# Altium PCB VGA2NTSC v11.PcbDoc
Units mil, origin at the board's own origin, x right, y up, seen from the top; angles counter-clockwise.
Board outline 2300 x 4000 mil, 2 copper layers (Top Layer, Bottom Layer), stack 62.8 mil thick; 49 components, 41 nets, 184 pads, 29 vias.
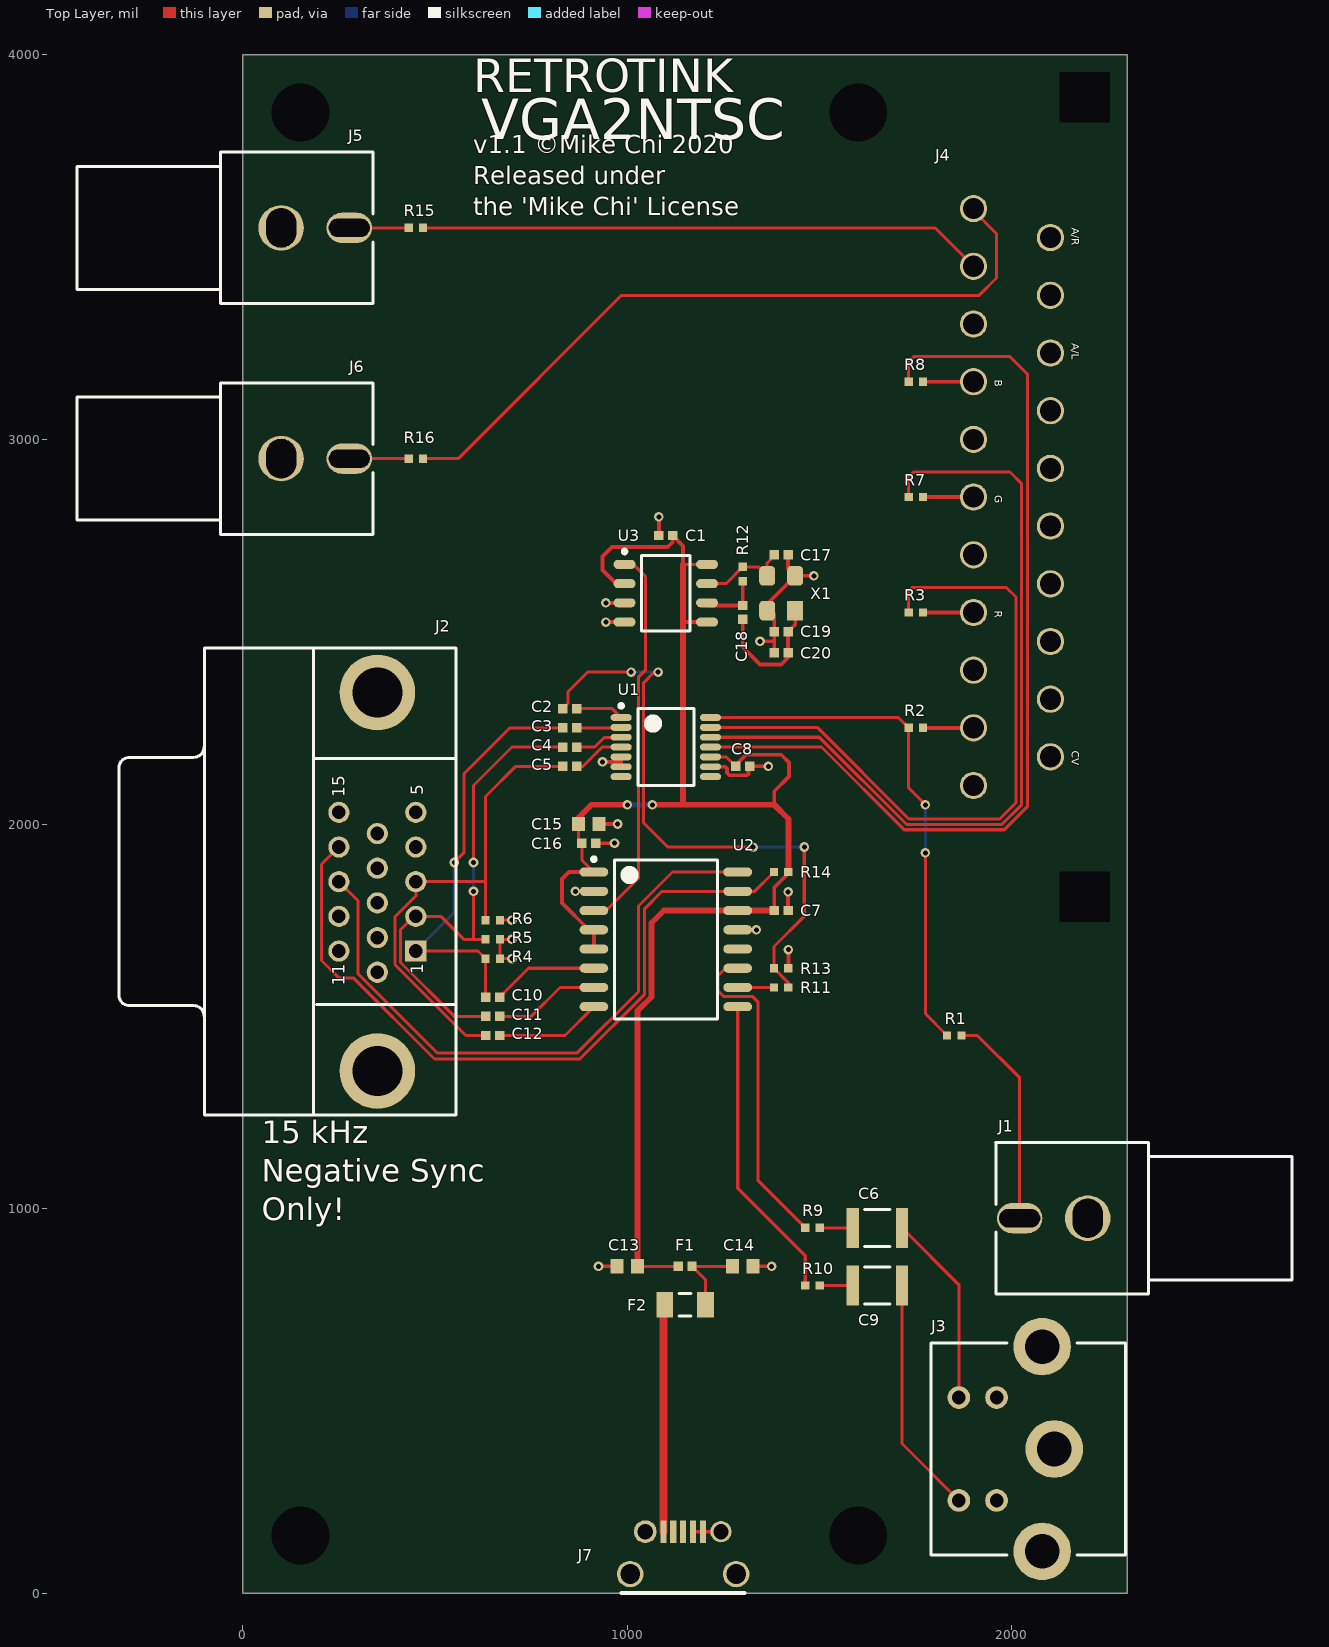
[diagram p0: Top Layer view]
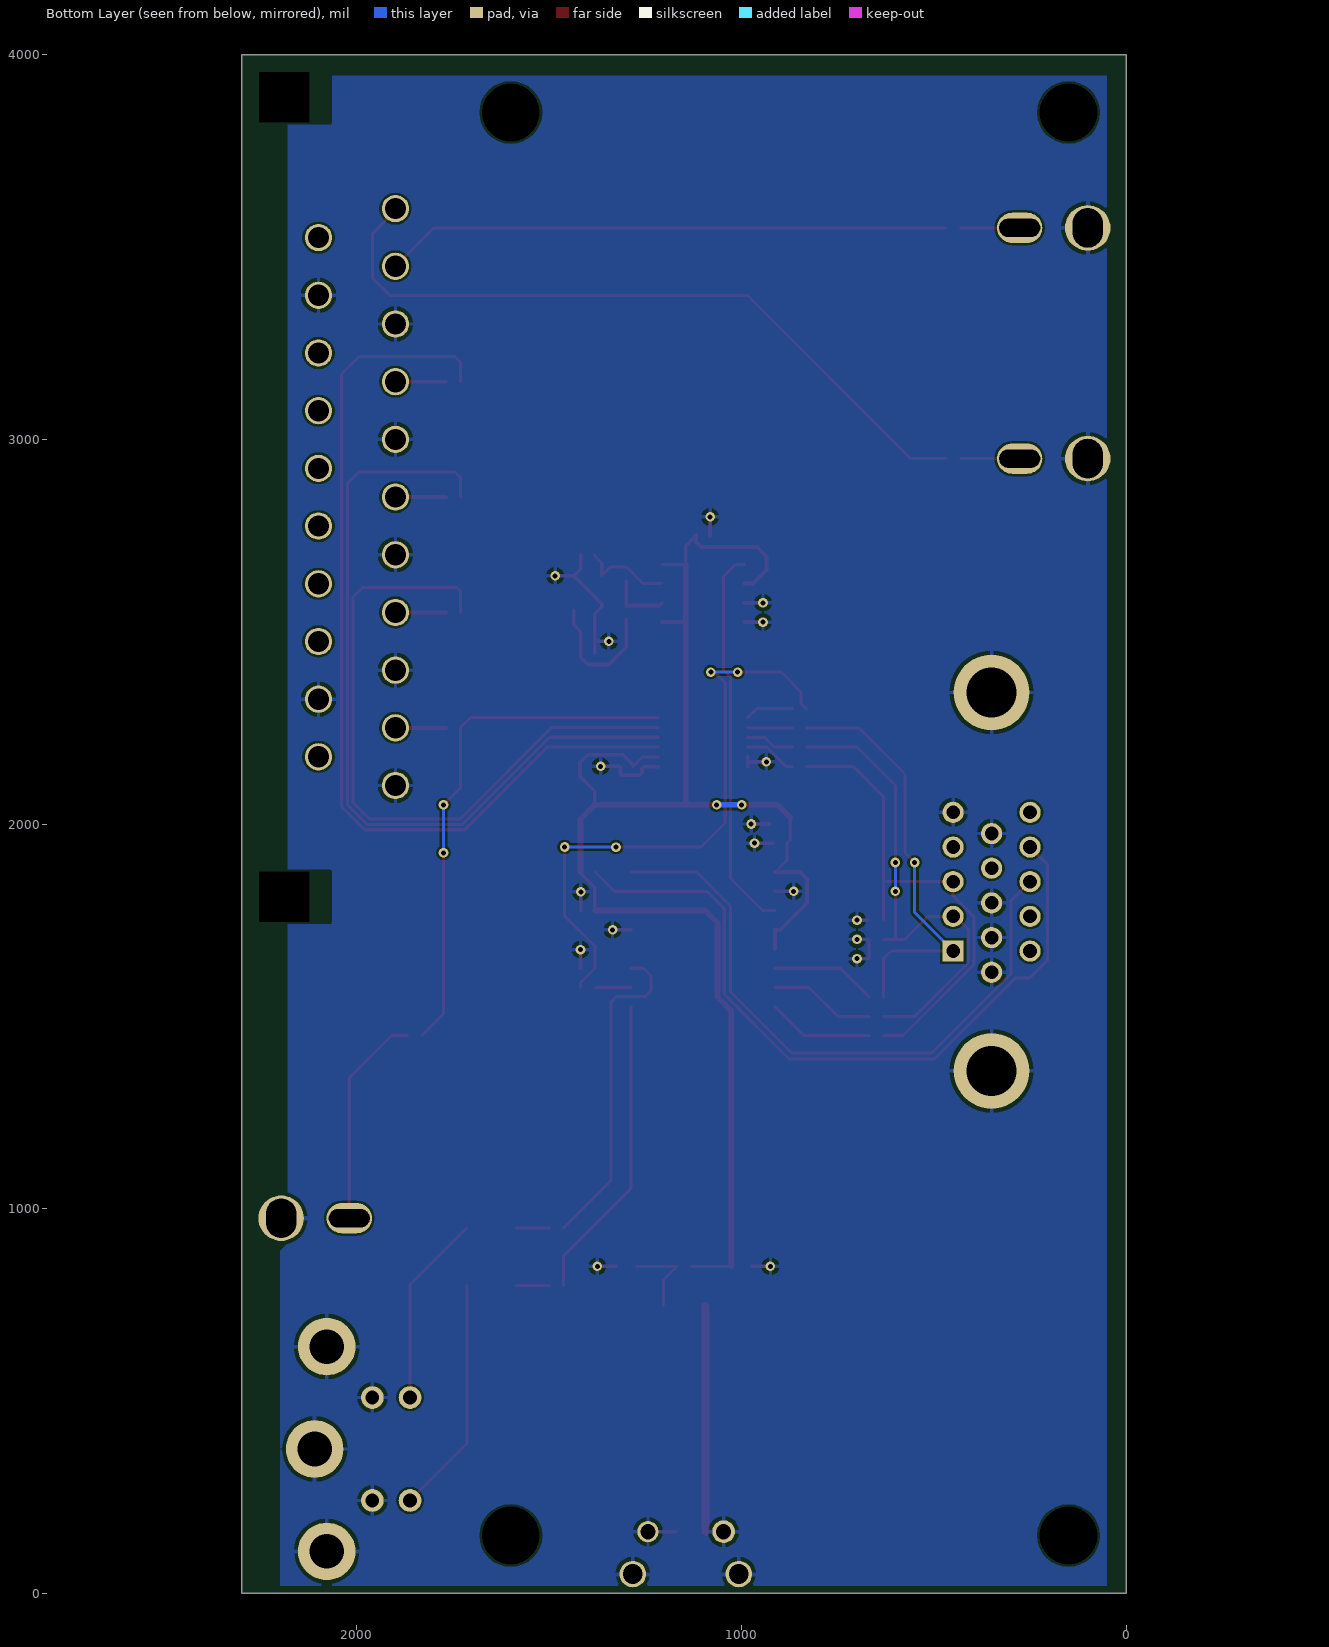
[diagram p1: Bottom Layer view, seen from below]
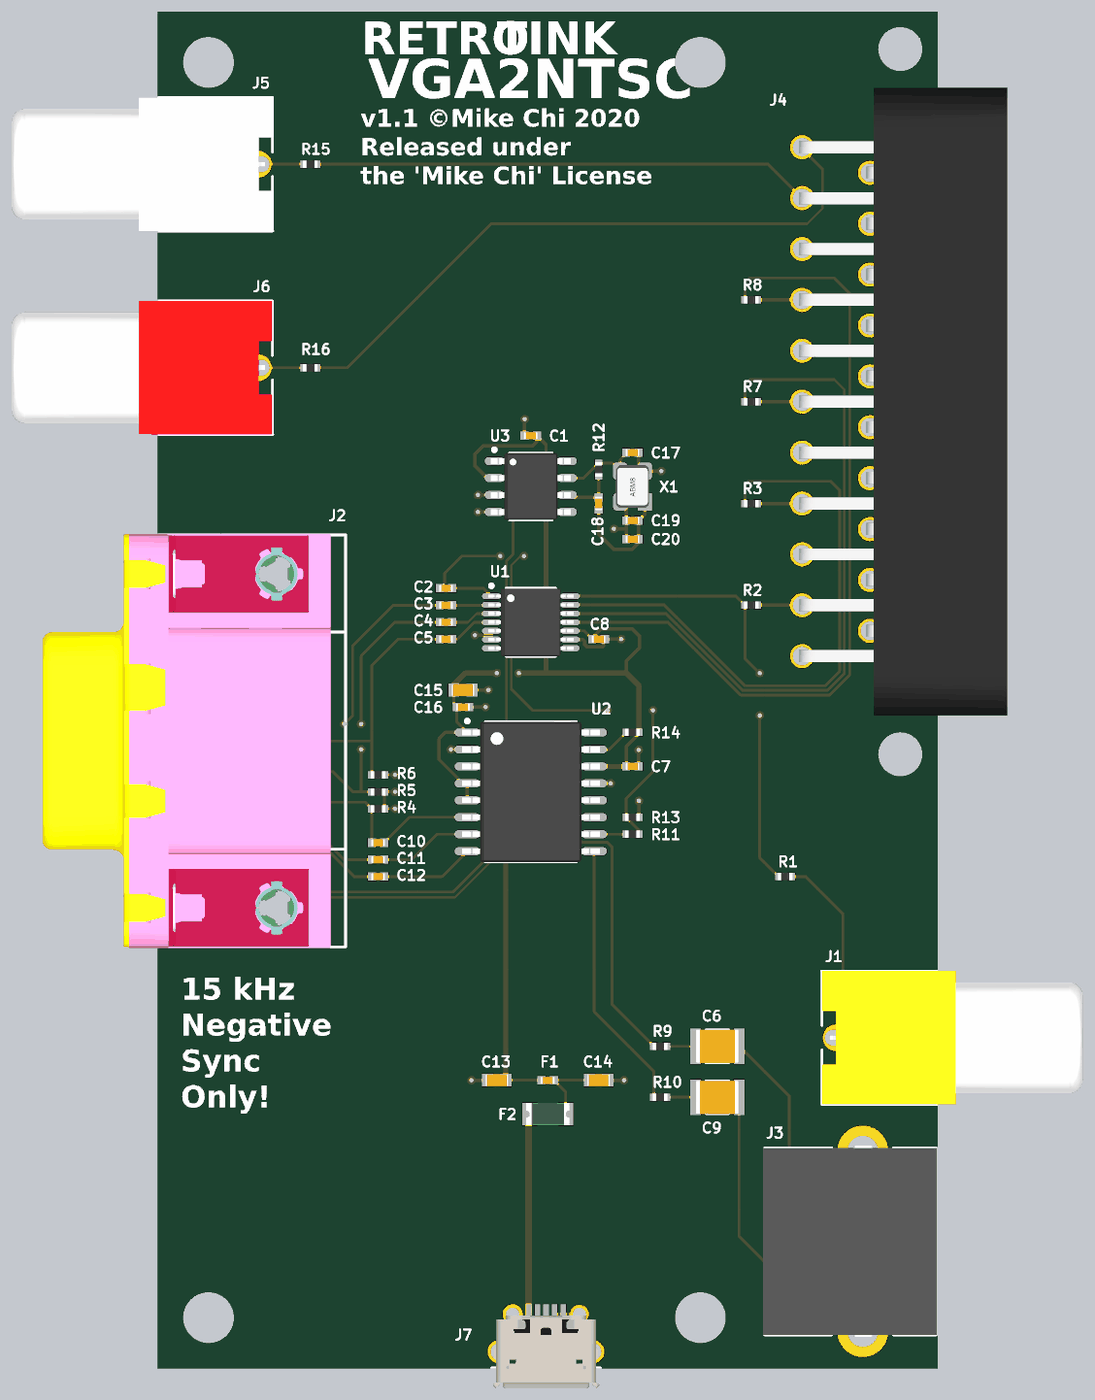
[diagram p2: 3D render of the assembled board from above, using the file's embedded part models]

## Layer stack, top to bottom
Top Solder: solder mask 0.4, Solder Resist, Dk 3.5
Top Layer: signal copper 1.4
Dielectric 1: dielectric 60, FR-4, Dk 4.8
Bottom Layer: signal copper 1.4
Bottom Solder: solder mask 0.4, Solder Resist, Dk 3.5

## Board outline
0,0 0,4000 2300,4000 2300,0

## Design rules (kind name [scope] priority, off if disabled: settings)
Clearance [All] p1: gap=6 ignorepadtopadclearanceinfootprint=FALSE
PlaneClearance [All] p1: clearance=15
PlaneConnect [All] p1: planeconnectstyle=Relief reliefexpansion=10 reliefentries=4 reliefconductorwidth=10 reliefairgap=6
PolygonConnect [All] p1: connectstyle=Relief reliefconductorwidth=10 reliefentries=4 polygonreliefangle="90 Angle" airgapwidth=10
RoutingVias [All] p1: holewidth=13 width=25 viastyle="Through Hole" minholewidth=13 minwidth=25 maxholewidth=13 maxwidth=25
SolderMaskExpansion [All] p1: expansion=2
Width [All] p1: maxlimit=20 minlimit=6 preferedwidth=6
28 further rules are at their usual default settings.

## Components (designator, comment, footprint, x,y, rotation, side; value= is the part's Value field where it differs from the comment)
C1 "Cap 0.1uF 0402" CAPC1005X05N 1100,2750 r0 top value=0.1uF
C2 "Cap 0.1uF 0402" CAPC1005X05N 850,2300 r0 top value=0.1uF
C3 "Cap 0.1uF 0402" CAPC1005X05N 850,2250 r0 top value=0.1uF
C4 "Cap 0.1uF 0402" CAPC1005X05N 850,2200 r0 top value=0.1uF
C5 "Cap 0.1uF 0402" CAPC1005X05N 850,2150 r0 top value=0.1uF
C6 "Cap 100uF 1210" CAPC3225X25N 1650,950 r0 top value=100uF
C7 "Cap 0.1uF 0402" CAPC1005X05N 1400,1775 r180 top value=0.1uF
C8 "Cap 0.1uF 0402" CAPC1005X05N 1300,2150 r180 top value=0.1uF
C9 "Cap 100uF 1210" CAPC3225X25N 1650,800 r0 top value=100uF
C10 "Cap 0.1uF 0402" CAPC1005X05N 650,1550 r0 top value=0.1uF
C11 "Cap 0.1uF 0402" CAPC1005X05N 650,1500 r0 top value=0.1uF
C12 "Cap 0.1uF 0402" CAPC1005X05N 650,1450 r0 top value=0.1uF
C13 "Cap 10uF 0603" CAPC1608X09N 1000,850 r180 top value=10uF
C14 "Cap 10uF 0603" CAPC1608X09N 1300,850 r0 top value=10uF
C15 "Cap 10uF 0603" CAPC1608X09N 900,2000 r0 top value=10uF
C16 "Cap 0.1uF 0402" CAPC1005X05N 900,1950 r180 top value=0.1uF
C17 "Cap 18pF 0402" CAPC1005X05N 1400,2700 r180 top value=18pF
C18 "Cap 47pF 0402" CAPC1005X05N 1300,2550 r270 top value=47pF
C19 "Cap 47pF 0402" CAPC1005X05N 1400,2500 r0 top value=47pF
C20 "Cap 47pF 0402" CAPC1005X05N 1400,2445 r0 top value=47pF
F1 "Ferrite Bead" CAPC1005X05N 1150,850 r0 top
F2 "PTC 500mA" PTC1206 1150,750 r180 top
J1 "RCA Yellow" RCJ-044 2197.01,975 r0 top
J2 "DB-15 VGA" "DB-15 VGA" 350,1850 r90 top
J3 "MD-40SM" CDIN2.6-3H4A 2295.04,375 r180 top
J4 "SCART Female" "SCART FEMALE" 1900,2850 r270 top
J5 "RCA White" RCJ-043 100,3550 r180 top
J6 "RCA Red" RCJ-042 100,2950 r180 top
J7 "Micro USB" MICROUSB 1145,189.53 r90 top
R1 "Res 75 0402" RESC1005X03N 1850,1450 r0 top value=75
R2 "Res 75 0402" RESC1005X03N 1750,2250 r0 top value=75
R3 "Res 75 0402" RESC1005X03N 1750,2550 r0 top value=75
R4 "Res 75 0402" RESC1005X03N 650,1650 r0 top value=75
R5 "Res 75 0402" RESC1005X03N 650,1700 r0 top value=75
R6 "Res 75 0402" RESC1005X03N 650,1750 r0 top value=75
R7 "Res 75 0402" RESC1005X03N 1750,2850 r0 top value=75
R8 "Res 75 0402" RESC1005X03N 1750,3150 r0 top value=75
R9 "Res 75 0402" RESC1005X03N 1481.3,950 r0 top value=75
R10 "Res 75 0402" RESC1005X03N 1481.3,800 r0 top value=75
R11 "Res 1k 0402" RESC1005X03N 1400,1575 r0 top value=1k
R12 "Res 1M 0402" RESC1005X03N 1300,2650 r270 top value=1M
R13 "Res 1k 0402" RESC1005X03N 1400,1625 r0 top value=1k
R14 "Res 4.7k" RESC1005X03N 1400,1875 r180 top value=4.7k
R15 "Res 49.9 0402" RESC1005X03N 450,3550 r180 top value=49.9
R16 "Res 49.9 0402" RESC1005X03N 450,2950 r180 top value=49.9
U1 "Video Buffer" TSOP65P640X120-14N 1100,2200 r0 top
U2 "Encoder" SOIC127P1030X237-16N 1100,1700 r0 top
U3 "OSC/DIV" SOIC127P600X175_HS-8N 1100,2600 r0 top
X1 "XTAL" ABM8-28.63636MHZ-B2-T 1400,2600 r90 top

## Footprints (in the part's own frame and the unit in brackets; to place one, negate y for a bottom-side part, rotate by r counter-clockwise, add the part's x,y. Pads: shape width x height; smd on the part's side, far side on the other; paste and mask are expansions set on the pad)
ABM8-28.63636MHZ-B2-T [mm] "ABM8-28.63636MHZ-B2-T"
  rect 1.3x1.05 smd: 1(-1.15,-0.925)
  rrect50% 1.3x1.05 smd: 2(1.15,-0.925) 3(1.15,0.925) 4(-1.15,0.925)
  body extent -1.6,-1.24 1.6,1.24, height 0.8
CAPC1005X05N [mm] "Chip Capacitor, 2-Leads, Body 1.00x0.50mm, IPC Medium Density"
  rect 0.62x0.62 smd: 1(-0.46,0) 2(0.46,0)
  body extent -0.53,-0.28 0.53,0.28, height 0.5
CAPC1608X09N [mm] "Chip Capacitor, 2-Leads, Body 1.60x0.80mm, IPC Medium Density"
  rect 0.85x0.95 smd: 1(-0.675,0) 2(0.675,0)
  body extent -0.85,-0.45 0.85,0.45, height 0.9
CAPC3225X25N [mm] "Chip Capacitor, 2-Leads, Body 3.20x2.50mm, IPC Medium Density"
  rect 0.8x2.65 smd: 1(-1.625,0) 2(1.625,0)
  silkscreen extent -0.85,-1.22 0.85,1.23, body extent -1.6,-1.25 1.6,1.25, height 2.5
CDIN2.6-3H4A [mm] "Connector; Circular DIN, Thru-Hole; 4 Position; Right Angle; Pitch 2.1/2.6 mm; Body 14 x 12.84 x 13 mm (WxTxH), Shielded, Special PCB Retention"
  round 1.5 hole 0.9: 1(8.51,-3.4) 2(8.51,3.4) 3(11,-3.4) 4(11,3.4)
  round 3.8 hole 2.28: MH1(5.5,-6.76) MH2(4.7,0) MH3(5.5,6.76)
  silkscreen extent 0,-7 12.84,7, body extent -0.05,-7.17 12.95,7.17, height 12.8
"DB-15 VGA" [mm]
  rect 1.4x1.4 hole 0.9: 1(-4.58,-2.54)
  round 1.4 hole 0.9: 2(-2.29,-2.54) 3(0,-2.54) 4(2.29,-2.54) 5(4.58,-2.54) 6(-5.98,0) 7(-3.69,0) 8(-1.4,0) 9(0.89,0) 10(3.18,0) 11(-4.58,2.54) 12(-2.29,2.54) 13(0,2.54) 14(2.29,2.54) 15(4.58,2.54)
  round 5 hole 3.3: 16(-12.495,0) 17(12.495,0)
  silkscreen extent -15.41,-5.19 15.43,17.07, body extent -15.5,-4.06 15.5,17.52, height 12.55
MICROUSB [mm]
  rect 1.5x0.4 smd: 1(-0.75,1.3) 2(-0.75,0.65) 3(-0.75,0) 4(-0.75,-0.65) 5(-0.75,-1.3)
  round 1.5 hole 1: 6(-0.75,2.5)
  round 1.4 hole 1: 7(-0.75,-2.5)
  round 1.75 hole 1.3: 8(-3.55,3.5) 9(-3.55,-3.5)
  silkscreen extent -4.8,-4.06 -4.8,4.06, body extent -6.28,-3.99 -0.85,3.99, height 2.73
PTC1206 [mm] "1206 PTC Fuse"
  rect 1.1x1.7 smd: 1(-1.35,0) 2(1.35,0)
  silkscreen extent -0.4,-0.75 0.4,0.75, body extent -1.63,-0.82 1.63,0.82, height 0.82
RCJ-042 [mm] "RCA Red"
  round 3 hole 2 slot 2.6 at 90 deg: 1A(0,0)
  oval 3x2 hole 1.2 slot 2.7 at 0 deg: 2B(-4.496,0)
  silkscreen extent -6.07,-5 13.5,5, body extent -6.04,-5 13.46,5, height 11.5
RCJ-043 [mm] "RCA White"
  round 3 hole 2 slot 2.6 at 90 deg: 1A(0,0)
  oval 3x2 hole 1.2 slot 2.7 at 0 deg: 2B(-4.496,0)
  silkscreen extent -6.07,-5 13.5,5, body extent -6.04,-5 13.46,5, height 11.5
RCJ-044 [mm] "RCA Yellow"
  round 3 hole 2 slot 2.6 at 90 deg: 1A(0,0)
  oval 3x2 hole 1.2 slot 2.7 at 0 deg: 2B(-4.496,0)
  silkscreen extent -6.07,-5 13.5,5, body extent -6.04,-5 13.46,5, height 11.5
RESC1005X03N [mm] "Chip Resistor, 2-Leads, Body 1.00x0.50mm, IPC Medium Density"
  rect 0.55x0.55 smd: 1(-0.475,0) 2(0.475,0)
  body extent -0.55,-0.28 0.55,0.28, height 0.35
"SCART FEMALE" [mm]
  round 1.8 hole 1.4: 1(-19.05,0) 2(-17.135,5.08) 3(-15.24,0) 4(-13.325,5.08) 5(-11.43,0) 6(-9.515,5.08) 7(-7.62,0) 8(-5.705,5.08) 9(-3.81,0) 10(-1.895,5.08) 11(0,0) 12(1.915,5.08) 13(3.81,0) 14(5.725,5.08) 15(7.62,0) 16(9.535,5.08) 17(11.43,0) 18(13.345,5.08) 19(15.24,0) 20(17.155,5.08) 21(19.05,0)
  round 0 hole 3.3 square unplated: ""(-26.4,7.35) ""(26.4,7.35)
  body extent -23.5,-0.25 23.5,15.35, height 16.75
SOIC127P600X175_HS-8N [mm] "SOIC, 8-Leads, Body 4.90x3.90mm, Pitch 1.27mm, NO Pad 2.39x2.39mm, IPC Medium Density"
  oval 1.45x0.6 smd: 1(-2.725,1.905) 2(-2.725,0.635) 3(-2.725,-0.635) 4(-2.725,-1.905) 5(2.725,-1.905) 6(2.725,-0.635) 7(2.725,0.635) 8(2.725,1.905)
  silkscreen extent -2.85,-2.5 1.6,2.88, body extent -3,-2.5 3,2.5, height 1.75
SOIC127P1030X237-16N [mm] "SOIC, 16-Leads, Body 10.25x7.50mm, Pitch 1.27mm, IPC Medium Density"
  oval 1.9x0.6 smd: 1(-4.75,4.445) 2(-4.75,3.175) 3(-4.75,1.905) 4(-4.75,0.635) 5(-4.75,-0.635) 6(-4.75,-1.905) 7(-4.75,-3.175) 8(-4.75,-4.445) 9(4.75,-4.445) 10(4.75,-3.175) 11(4.75,-1.905) 12(4.75,-0.635) 13(4.75,0.635) 14(4.75,1.905) 15(4.75,3.175) 16(4.75,4.445)
  silkscreen extent -4.87,-5.25 3.4,5.42, body extent -5.16,-5.25 5.16,5.25, height 2.36
TSOP65P640X120-14N [mm] "TSOP, 14-Leads, Body 5.00x4.40mm, Pitch 0.65mm, IPC Medium Density"
  oval 1.4x0.45 smd: 1(-2.95,1.95) 2(-2.95,1.3) 3(-2.95,0.65) 4(-2.95,0) 5(-2.95,-0.65) 6(-2.95,-1.3) 7(-2.95,-1.95) 8(2.95,-1.95) 9(2.95,-1.3) 10(2.95,-0.65) 11(2.95,0) 12(2.95,0.65) 13(2.95,1.3) 14(2.95,1.95)
  silkscreen extent -3.07,-2.55 1.85,2.85, body extent -3.2,-2.55 3.2,2.55, height 1.2

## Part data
C1 C2 C3 C4 C5 C7 C8 C10 C11 C12 C16: "Capacitor", Dielectric=X7R, ManufacturerPartNumber=CL05B104JO5NNNC, Voltage=16V
C6 C9: "Capacitor", Dielectric=X5R, ManufacturerPartNumber=GRM32ER61A107ME20L, Voltage=10V
C13 C14 C15: "Capacitor", Dielectric=X5R, ManufacturerPartNumber=GRM188R61A106KE69J, Voltage=10V
C17: "Capacitor", Dielectric=C0G, ManufacturerPartNumber=CL05C180JB5NNNC, Voltage=50V
C18 C19 C20: library part "Cap 47pF", "Capacitor", Dielectric=C0G, ManufacturerPartNumber=C0402C470K5GACTU, Voltage=50V
F1: library part BLM15PX221SN1D, "Ferrite Bead 220 Ohm 100Mhz 100mOhm DC"
F2: library part "PTC Fuse", "PTC Fuse 500mA", ManufacturerPartNumber=0ZCJ0050AF2E
J1: library part RCJ-044, "RCA Jack Yellow"
J2: ManufacturerPartNumber=ICD15S13E4GX00LF
J3: "DIN-4 S-Video Jack"
J4: library part SCART
J5: library part RCJ-043, "RCA Jack White"
J6: library part RCJ-042, "RCA Jack Red"
J7: library part MICROUSB, ManufacturerPartNumber=10118194-0001LF
R1 R2 R3 R4 R5 R6 R7 R8 R9 R10: "Resistor 75 0402", ManufacturerPartNumber=RC0402FR-0775RL, Tolerance=1%
R11 R13: "Resistor 1k 0402", ManufacturerPartNumber=RC1005F102CS, Tolerance=1%
R12: "Resistor 1M 0402", ManufacturerPartNumber=RC1005F105CS, Tolerance=1%
R14: library part "Res 4.7k 0402", "Resistor 4.7k 0402", ManufacturerPartNumber=RCS1005J472CS, Tolerance=5%
R15 R16: "Resistor 49.9 0402", ManufacturerPartNumber=RC1005F49R9CS, Tolerance=1%
U1: library part TSH7373, ManufacturerPartNumber=THS7373IPWR
U2: library part AD725ARZ, "RGB to Video Encoder"
U3: library part 74HC6323AD, "Counter + Oscillator"
X1: library part ABM8-28.63636MHZ-B2-T, "CRYSTAL 28.63636MHZ 18PF SMD"

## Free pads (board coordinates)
  round 60 hole 150 unplated: ""(150,150) ""(150,3850) ""(1600,150) ""(1600,3850)

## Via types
v1: diameter 25, hole 13, Top Layer to Bottom Layer, tented both sides, 29 vias

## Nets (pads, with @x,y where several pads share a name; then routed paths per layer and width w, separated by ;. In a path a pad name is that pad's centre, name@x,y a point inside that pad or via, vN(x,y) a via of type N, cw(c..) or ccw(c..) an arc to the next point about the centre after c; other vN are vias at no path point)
BIN: C5.1 C12.1 J2.3 R6.1 | length 1286.1
  Top Layer w8: R6.1 631.3,1850 ; C12.1 580.2,1450 396,1634.2 396,1758.96 450,1812.96 J2.3 631.3,1850 ; C5.1 710,2150 631.3,2071.3 631.3,1850
BOUT: J4.7 R8.2 | length 131.3
  Top Layer w10: R8.2 J4.7
CHROMA_OUT: C9.2 J3.4 | length 620.2
  Top Layer w8: C9.2 1713.98,389.13 J3.4
CLOCK: U2.3 U3.1 | length 1010.2
  Top Layer w8: U2.3 945,1775 1028.5,1858.5 1028.5,2381.68 1047.5,2400.68 1047.5,2642.5 1015,2675 U3.1
CSYNC_OUT: J4.19 R2.2 | length 131.3
  Top Layer w10: R2.2 J4.19
CVBS_OUT: J1.2B R1.2 | length 561.9
  Top Layer w8: R1.2 1910,1450 2020,1340 J1.2B
GIN: C4.1 C11.1 J2.2 R5.1 | length 1298.7
  Top Layer w8: v1(600,1825) 600,1700 ; v1(600,1900) 600,2100 700,2200 C4.1 ; R5.1 600,1700 ; C11.1 550,1500 410,1640 410,1725 444.84,1759.84 J2.2 515.16,1759.84 575,1700 600,1700
  Bottom Layer w8: v1(600,1825) v1(600,1900)
GND: C1.1 C7.1 C8.1 C13.2 C14.2 C15.2 C16.1 C17.1 C19.1 C20.1 J1.1A J2.5 J2.6 J2.7 J2.8 J2.10 J2.16 J2.17 J3.1 J3.2 J3.MH1 J3.MH2 J3.MH3 J4.4 J4.5 J4.9 J4.13 J4.17 J4.18 J4.21 J5.1A J6.1A J7.4 J7.5 J7.6 J7.7 J7.8 J7.9 R4.2 R5.2 R6.2 R13.2 U1.5 U1.6 U1.9 U2.2 U2.13 U3.3 U3.4 X1.2 X1.4 | length 1394.7
  Top Layer w8: R6.2 v1(700,1750) ; v1(700,1650) R4.2 R5.2 v1(700,1700)
  Top Layer w10: v1(864.57,1825) U2.2 ; C16.1 v1(966.54,1950) ; v1(925,850) C13.2 ; C15.2 v1(975,2000) ; v1(935.43,2161.61) 983.86,2161.61 ; v1(944.29,2525) U3.4 ; v1(944.29,2575) U3.3 ; U1.6 U1.5 ; C1.1 v1(1081.89,2798.43) ; J7.4 J7.5 J7.7 ; U1.9 1254.44,2148.82 1258.69,2144.57 1258.69,2133.24 1265.13,2126.8 1311.8,2126.8 1315,2130 1315,2146.89 C8.1 v1(1366.54,2150) ; U2.13 v1(1335.43,1725) ; C14.2 v1(1375,850) ; v1(1345,2475) 1381.89,2475 ; C20.1 1381.89,2475 ; C7.1 v1(1418.11,1823.43) ; C17.1 1418.11,2663.58 X1.2 ; R13.2 v1(1418.7,1673.43) ; v1(1484.84,2645.28) X1.2 ; 1381.89,2475 C19.1 1381.89,2546.69 1363.58,2565 1363.58,2572.44 X1.2
GOUT: J4.11 R7.2 | length 131.3
  Top Layer w10: R7.2 J4.11
HS: J2.13 U2.16 | length 1662.7
  Top Layer w8: J2.13 300,1800 300,1610.04 505.04,1405 870,1405 1029,1564 1029,1786.63 1117.37,1875 U2.16
  Bottom Layer w10: J2.13 J2.13@255,1850
LUMA_OUT: C6.2 J3.3 | length 502.4
  Top Layer w8: C6.2 1861.97,802.01 J3.3
NetC2_1: C2.1 R11.2 R13.1 | length 1575.7
  Top Layer w8: C2.1 845.91,2314.02 845.91,2344.08 896.82,2395 v1(1010,2395) ; v1(1080,2395) 1070,2395 1042.5,2367.5 1042.5,2002.5 1105,1940 v1(1326.65,1940) ; R11.2 1418.7,1587.6 R13.1 1381.3,1681.3 1460,1760 v1(1460,1940.16)
  Bottom Layer w8: v1(1010,2395) v1(1080,2395) ; v1(1326.65,1940) 1326.81,1940.16 v1(1460,1940.16)
NetC2_2: C2.2 U1.1 | length 125.4
  Top Layer w8: C2.2 960.63,2300 U1.1
NetC3_2: C3.2 U1.2 | length 116.2
  Top Layer w8: C3.2 982.68,2250 U1.2
NetC4_2: C4.2 U1.3 | length 126.3
  Top Layer w8: C4.2 915,2200 940,2225 983.27,2225 U1.3
NetC5_2: C5.2 U1.4 | length 136.5
  Top Layer w8: C5.2 884.8,2150 934.8,2200 U1.4
NetC6_1: C6.1 R9.2 | length 86
  Top Layer w8: R9.2 C6.1
NetC9_1: C9.1 R10.2 | length 86
  Top Layer w8: R10.2 C9.1
NetC10_2: C10.2 U2.6 | length 275.9
  Top Layer w8: C10.2 743.11,1625 U2.6
NetC11_2: C11.2 U2.7 | length 275.9
  Top Layer w8: C11.2 750,1500 825,1575 U2.7
NetC12_2: C12.2 U2.8 | length 275.9
  Top Layer w8: C12.2 837.99,1450 U2.8
NetC14_1: C14.1 F1.2 F2.1 | length 219.8
  Top Layer w8: F2.1 1203.15,814.96 F1.2 C14.1
NetC17_2: C17.2 R12.1 U3.7 X1.3 | length 246.4
  Top Layer w8: U3.7 1256.3,2625 R12.1 1340.16,2668.7 X1.3 1363.58,2678.58 1381.89,2696.89 C17.2
NetC18_1: C18.1 R12.2 U3.6 | length 158.8
  Top Layer w10: U3.6 1214.17,2568.11 C18.1 R12.2
NetC18_2: C18.2 C19.2 C20.2 X1.1 | length 345.3
  Top Layer w10: C18.2 1300,2530 1300,2460 1345,2415 1400,2415 1418.11,2433.11 C20.2 1418.11,2493.11 C19.2 1436.42,2518.31 X1.1
NetF2_2: F2.2 J7.1 | length 594
  Top Layer w8: F2.2@1093.82,746.97 F2.2 F2.2@1098.82,748.03
  Top Layer w20: J7.1 F2.2@1093.82,746.97
NetJ4_1: J4.1 R16.1 | length 1891.1
  Top Layer w8: R16.1 560,2950 984.61,3374.61 1915,3374.61 1960,3419.61 1960,3535 1900,3595 J4.1
NetJ4_3: J4.3 R15.1 | length 1472.7
  Top Layer w8: R15.1 1800,3550 J4.3
NetJ5_2B: J5.2B R15.2 | length 154.3
  Top Layer w8: J5.2B R15.2
NetJ6_2B: J6.2B R16.2 | length 154.3
  Top Layer w8: J6.2B R16.2
NetR1_1: R1.1 R2.1 U1.14 | length 1367.7
  Top Layer w8: U1.14 1704.53,2276.77 R2.1 1731.3,2093.7 v1(1775,2050) ; v1(1775,1925) 1775,1506.3 R1.1
  Bottom Layer w8: v1(1775,1925) v1(1775,2050)
NetR3_1: R3.1 U1.13 | length 1794.5
  Top Layer w8: U1.13 1493.42,2251.18 1731.6,2013 1968.4,2013 2010.3,2054.9 2010.3,2590 1985.3,2615 1740,2615 1731.3,2606.3 R3.1
NetR7_1: R7.1 U1.12 | length 2121.5
  Top Layer w8: U1.12 1499.21,2225.59 1725.8,1999 1974.2,1999 2024.3,2049.1 2024.3,2885.7 1995,2915 1745,2915 1731.3,2901.3 R7.1
NetR8_1: R8.1 U1.11 | length 2447.1
  Top Layer w8: U1.11 1505,2200 1720,1985 1980,1985 2040,2045 2040,3170 1995,3215 1745,3215 1731.3,3201.3 R8.1
NetR9_1: R9.1 U2.11 | length 853.4
  Top Layer w8: U2.11 1255,1625 1235,1605 1235,1566.81 1250,1551.81 1324.76,1551.81 1340,1536.57 1340,1072.6 R9.1
NetR10_1: R10.1 U2.9 | length 797.7
  Top Layer w8: U2.9 1287.01,1052.99 1462.6,877.4 R10.1
NetR11_1: R11.1 U2.10 | length 94.3
  Top Layer w8: U2.10 R11.1
RIN: C3.1 C10.1 J2.1 R4.1 | length 1108.4
  Top Layer w8: J2.1 611.61,1669.68 R4.1 631.3,1550.59 C10.1 ; v1(550,1900) 575,1925 575,2130 695,2250 C3.1
  Bottom Layer w8: J2.1 550,1769.68 v1(550,1900)
ROUT: J4.15 R3.2 | length 131.3
  Top Layer w10: R3.2 J4.15
VCC: C1.2 C7.2 C8.2 C13.1 C15.1 C16.2 F1.1 R14.1 U1.10 U2.1 U2.4 U2.5 U2.14 U3.2 U3.5 U3.8 | length 4166.4
  Top Layer w8: C15.1 873.43,1958.46 C16.2 881.89,1906.1 U2.1 ; C13.1 F1.1 ; 1145,2675 U3.8 ; U1.10 1257.48,2174.41 C8.2
  Top Layer w10: C15.1 C15.1@873.43,2016.6 ; U2.5 U2.4 899.8,1725 830,1794.8 830,1856.61 848.39,1875 U2.1 ; U3.2 970.43,2625 935.43,2660 935.43,2695.43 960,2720 1105,2720 1118.11,2733.11 C1.2 1145,2723.11 1145,2675 ; 1145,2525 U3.5 ; C8.2 1281.89,2153.75 1308.14,2180 1400,2180 1420,2160 1420,2123.23 1381.89,2085.12 1381.89,2050 ; C7.2 1381.89,1835.2 1418.7,1872.01 R14.1
  Top Layer w15: C15.1@873.43,2016.6 906.82,2050 v1(1000,2050) ; C13.1 1026.57,1514.2 1062.5,1550.12 1062.5,1742.5 1095,1775 U2.14 C7.2 ; v1(1065,2050) 1145,2050 ; 1145,2675 1145,2525 1145,2050 ; R14.1 1418.7,2013.19 1381.89,2050 1145,2050
  Bottom Layer w15: v1(1000,2050) v1(1065,2050)
VS: J2.14 R14.2 U2.15 | length 1927.9
  Top Layer w8: J2.14 205,1895.16 205,1645 250,1600 287.41,1600 498.41,1389 876.63,1389 1045,1557.37 1045,1780 1090,1825 U2.15 1331.3,1825 R14.2
pads on no net: J2.4 J2.9 J2.11 J2.12 J2.15 J4. J4.2 J4.6 J4.8 J4.10 J4.12 J4.14 J4.16 J4.20 J7.2 J7.3 U1.7 U1.8 U2.12

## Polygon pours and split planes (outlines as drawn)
GND on Bottom Layer "Bottom Layer-GND" (solid, pour order 0): 50,20 2200,20 2200,890 2180,910 2180,3945 50,3945

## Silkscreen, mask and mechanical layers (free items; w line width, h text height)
Top Overlay:
  text "RETRO" at 600,3874.41 h150
  text "TINK" at 1000,3874.41 h150
  text "VGA2NTSC" at 620,3745 h180
  text "v1.1 ©Mike Chi 2020 / Released under  / the 'Mike Chi' License" at 600,3567.72 h80
  text "15 kHz / Negative Sync / Only!" at 50,950 h100
Mechanical 1:
  the board outline again, w10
